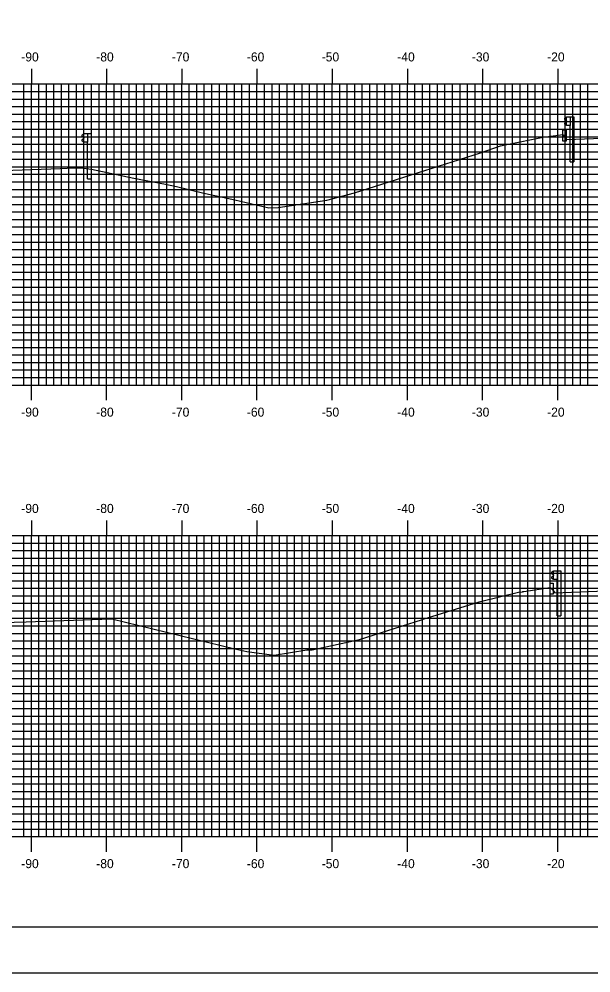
# Model space of a CAD drawing. Extents: x 858445 to 858788, y 364366 to 364586.
# Drawn here: x 858519.2 to 858595.3, y 364365.7 to 364492.4 of the extents above; entities that cross this region are included whole.
import ezdxf

# ---------------------------------------------------------------- set-up
doc = ezdxf.new("R2010")
doc.units = 0
for name, color, linetype in [('BORDER', 7, 'Continuous'), ('H_V ANNOTATION', 7, 'Continuous'), ('M_Guardrail', 7, 'Continuous'), ('MAJOR', 7, 'Continuous'), ('MINOR', 7, 'Continuous'), ('PLOT BOUNDARY', 7, 'Continuous'), ('S_Curb_Type_1', 7, 'Continuous'), ('S_Guardrail_Beam', 7, 'Continuous'), ('S_Roadway_Centerline', 7, 'Continuous')]:
    doc.layers.add(name, color=color, linetype=linetype)

msp = doc.modelspace()

# ---------------------------------------------------------------- linework, layer by layer
at = {"layer": 'BORDER'}
msp.add_lwpolyline([(858461.27, 364371.79), (858781.27, 364371.79), (858781.27, 364581.79), (858461.27, 364581.79)], close=True, dxfattribs=at)
at = {"layer": 'M_Guardrail'}
for p, q in [((858527.76, 364477.11), (858527.61, 364477.01)), ((858527.61, 364476.87), (858527.81, 364476.73)), ((858527.85, 364477.13), (858527.77, 364477.12)), ((858527.84, 364476.67), (858527.84, 364476.57)), ((858527.85, 364477.2), (858528.34, 364477.2)), ((858527.85, 364476.04), (858527.85, 364477.2)), ((858528.34, 364477.2), (858528.84, 364477.2)), ((858528.34, 364477.2), (858528.34, 364476.04)), ((858528.84, 364477.2), (858528.84, 364471.2)), ((858527.81, 364476.51), (858527.61, 364476.37)), ((858527.61, 364476.23), (858527.76, 364476.13)), ((858527.77, 364476.12), (858527.85, 364476.11)), ((858528.34, 364476.04), (858527.85, 364476.04)), ((858528.34, 364471.2), (858528.34, 364476.04)), ((858528.34, 364471.2), (858528.84, 364471.2))]:
    msp.add_line(p, q, dxfattribs=at)
for centre, major_axis, start_param, end_param in [((858527.66, 364476.94), (-0.0877, 0), 5.323254, 7.243116), ((858527.78, 364477.08), (-0.0417, 0), 4.886922, 5.323254), ((858527.76, 364476.67), (0.0789, 0), 0, 0.959931), ((858527.76, 364476.57), (0.0789, 0), 5.323254, 6.283185), ((858527.66, 364476.3), (-0.0877, 0), 5.323254, 7.243116), ((858527.78, 364476.16), (-0.0417, 0), 0.959931, 1.396263)]:
    msp.add_ellipse(centre, major_axis=major_axis, ratio=0.995501, start_param=start_param, end_param=end_param, dxfattribs=at)
at = {"layer": 'MAJOR'}
for p, q in [((858520.87, 364485.79), (858520.87, 364483.79)), ((858530.87, 364485.79), (858530.87, 364483.79)), ((858540.87, 364485.79), (858540.87, 364483.79)), ((858550.87, 364485.79), (858550.87, 364483.79)), ((858560.87, 364485.79), (858560.87, 364483.79)), ((858570.87, 364485.79), (858570.87, 364483.79)), ((858580.87, 364485.79), (858580.87, 364483.79)), ((858590.87, 364485.79), (858590.87, 364483.79)), ((858470.87, 364483.79), (858750.87, 364483.79)), ((858470.87, 364483.79), (858750.87, 364483.79)), ((858520.87, 364443.79), (858520.87, 364483.79)), ((858530.87, 364443.79), (858530.87, 364483.79)), ((858540.87, 364443.79), (858540.87, 364483.79)), ((858550.87, 364443.79), (858550.87, 364483.79)), ((858560.87, 364443.79), (858560.87, 364483.79)), ((858570.87, 364443.79), (858570.87, 364483.79)), ((858580.87, 364443.79), (858580.87, 364483.79)), ((858590.87, 364443.79), (858590.87, 364483.79)), ((858470.87, 364478.79), (858750.87, 364478.79)), ((858470.87, 364473.79), (858750.87, 364473.79)), ((858470.87, 364468.79), (858750.87, 364468.79)), ((858470.87, 364463.79), (858750.87, 364463.79)), ((858470.87, 364458.79), (858750.87, 364458.79)), ((858470.87, 364453.79), (858750.87, 364453.79)), ((858470.87, 364448.79), (858750.87, 364448.79)), ((858470.87, 364443.79), (858750.87, 364443.79)), ((858470.87, 364443.79), (858750.87, 364443.79)), ((858520.87, 364441.78), (858520.87, 364443.79)), ((858530.87, 364441.78), (858530.87, 364443.79)), ((858540.87, 364441.78), (858540.87, 364443.79)), ((858550.87, 364441.78), (858550.87, 364443.79)), ((858560.87, 364441.78), (858560.87, 364443.79)), ((858570.87, 364441.78), (858570.87, 364443.79)), ((858580.87, 364441.78), (858580.87, 364443.79)), ((858590.87, 364441.78), (858590.87, 364443.79)), ((858520.87, 364425.79), (858520.87, 364423.79)), ((858530.87, 364425.79), (858530.87, 364423.79)), ((858540.87, 364425.79), (858540.87, 364423.79)), ((858550.87, 364425.79), (858550.87, 364423.79)), ((858560.87, 364425.79), (858560.87, 364423.79)), ((858570.87, 364425.79), (858570.87, 364423.79)), ((858580.87, 364425.79), (858580.87, 364423.79)), ((858590.87, 364425.79), (858590.87, 364423.79)), ((858470.87, 364423.79), (858750.87, 364423.79)), ((858470.87, 364423.79), (858750.87, 364423.79)), ((858520.87, 364383.79), (858520.87, 364423.79)), ((858530.87, 364383.79), (858530.87, 364423.79)), ((858540.87, 364383.79), (858540.87, 364423.79)), ((858550.87, 364383.79), (858550.87, 364423.79)), ((858560.87, 364383.79), (858560.87, 364423.79)), ((858570.87, 364383.79), (858570.87, 364423.79)), ((858580.87, 364383.79), (858580.87, 364423.79)), ((858590.87, 364383.79), (858590.87, 364423.79)), ((858470.87, 364418.79), (858750.87, 364418.79)), ((858470.87, 364413.79), (858750.87, 364413.79)), ((858470.87, 364408.79), (858750.87, 364408.79)), ((858470.87, 364403.79), (858750.87, 364403.79)), ((858470.87, 364398.79), (858750.87, 364398.79)), ((858470.87, 364393.79), (858750.87, 364393.79)), ((858470.87, 364388.79), (858750.87, 364388.79)), ((858470.87, 364383.79), (858750.87, 364383.79)), ((858470.87, 364383.79), (858750.87, 364383.79)), ((858520.87, 364381.78), (858520.87, 364383.79)), ((858530.87, 364381.78), (858530.87, 364383.79)), ((858540.87, 364381.78), (858540.87, 364383.79)), ((858550.87, 364381.78), (858550.87, 364383.79)), ((858560.87, 364381.78), (858560.87, 364383.79)), ((858570.87, 364381.78), (858570.87, 364383.79)), ((858580.87, 364381.78), (858580.87, 364383.79)), ((858590.87, 364381.78), (858590.87, 364383.79))]:
    msp.add_line(p, q, dxfattribs=at)
at = {"layer": 'MINOR'}
for p, q in [((858519.87, 364443.79), (858519.87, 364483.79)), ((858521.87, 364443.79), (858521.87, 364483.79)), ((858522.87, 364443.79), (858522.87, 364483.79)), ((858523.87, 364443.79), (858523.87, 364483.79)), ((858524.87, 364443.79), (858524.87, 364483.79)), ((858525.87, 364443.79), (858525.87, 364483.79)), ((858526.87, 364443.79), (858526.87, 364483.79)), ((858527.87, 364443.79), (858527.87, 364483.79)), ((858528.87, 364443.79), (858528.87, 364483.79)), ((858529.87, 364443.79), (858529.87, 364483.79)), ((858531.87, 364443.79), (858531.87, 364483.79)), ((858532.87, 364443.79), (858532.87, 364483.79)), ((858533.87, 364443.79), (858533.87, 364483.79)), ((858534.87, 364443.79), (858534.87, 364483.79)), ((858535.87, 364443.79), (858535.87, 364483.79)), ((858536.87, 364443.79), (858536.87, 364483.79)), ((858537.87, 364443.79), (858537.87, 364483.79)), ((858538.87, 364443.79), (858538.87, 364483.79)), ((858539.87, 364443.79), (858539.87, 364483.79)), ((858541.87, 364443.79), (858541.87, 364483.79)), ((858542.87, 364443.79), (858542.87, 364483.79)), ((858543.87, 364443.79), (858543.87, 364483.79)), ((858544.87, 364443.79), (858544.87, 364483.79)), ((858545.87, 364443.79), (858545.87, 364483.79)), ((858546.87, 364443.79), (858546.87, 364483.79)), ((858547.87, 364443.79), (858547.87, 364483.79)), ((858548.87, 364443.79), (858548.87, 364483.79)), ((858549.87, 364443.79), (858549.87, 364483.79)), ((858551.87, 364443.79), (858551.87, 364483.79)), ((858552.87, 364443.79), (858552.87, 364483.79)), ((858553.87, 364443.79), (858553.87, 364483.79)), ((858554.87, 364443.79), (858554.87, 364483.79)), ((858555.87, 364443.79), (858555.87, 364483.79)), ((858556.87, 364443.79), (858556.87, 364483.79)), ((858557.87, 364443.79), (858557.87, 364483.79)), ((858558.87, 364443.79), (858558.87, 364483.79)), ((858559.87, 364443.79), (858559.87, 364483.79)), ((858561.87, 364443.79), (858561.87, 364483.79)), ((858562.87, 364443.79), (858562.87, 364483.79)), ((858563.87, 364443.79), (858563.87, 364483.79)), ((858564.87, 364443.79), (858564.87, 364483.79)), ((858565.87, 364443.79), (858565.87, 364483.79)), ((858566.87, 364443.79), (858566.87, 364483.79)), ((858567.87, 364443.79), (858567.87, 364483.79)), ((858568.87, 364443.79), (858568.87, 364483.79)), ((858569.87, 364443.79), (858569.87, 364483.79)), ((858571.87, 364443.79), (858571.87, 364483.79)), ((858572.87, 364443.79), (858572.87, 364483.79)), ((858573.87, 364443.79), (858573.87, 364483.79)), ((858574.87, 364443.79), (858574.87, 364483.79)), ((858575.87, 364443.79), (858575.87, 364483.79)), ((858576.87, 364443.79), (858576.87, 364483.79)), ((858577.87, 364443.79), (858577.87, 364483.79)), ((858578.87, 364443.79), (858578.87, 364483.79)), ((858579.87, 364443.79), (858579.87, 364483.79)), ((858581.87, 364443.79), (858581.87, 364483.79)), ((858582.87, 364443.79), (858582.87, 364483.79)), ((858583.87, 364443.79), (858583.87, 364483.79)), ((858584.87, 364443.79), (858584.87, 364483.79)), ((858585.87, 364443.79), (858585.87, 364483.79)), ((858586.87, 364443.79), (858586.87, 364483.79)), ((858587.87, 364443.79), (858587.87, 364483.79)), ((858588.87, 364443.79), (858588.87, 364483.79)), ((858589.87, 364443.79), (858589.87, 364483.79)), ((858591.87, 364443.79), (858591.87, 364483.79)), ((858592.87, 364443.79), (858592.87, 364483.79)), ((858593.87, 364443.79), (858593.87, 364483.79)), ((858594.87, 364443.79), (858594.87, 364483.79)), ((858470.87, 364482.79), (858750.87, 364482.79)), ((858470.87, 364481.79), (858750.87, 364481.79)), ((858470.87, 364480.79), (858750.87, 364480.79)), ((858470.87, 364479.79), (858750.87, 364479.79)), ((858470.87, 364477.79), (858750.87, 364477.79)), ((858470.87, 364476.79), (858750.87, 364476.79)), ((858470.87, 364475.79), (858750.87, 364475.79)), ((858470.87, 364474.79), (858750.87, 364474.79)), ((858470.87, 364472.79), (858750.87, 364472.79)), ((858470.87, 364471.79), (858750.87, 364471.79)), ((858470.87, 364470.79), (858750.87, 364470.79)), ((858470.87, 364469.79), (858750.87, 364469.79)), ((858470.87, 364467.79), (858750.87, 364467.79)), ((858470.87, 364466.79), (858750.87, 364466.79)), ((858470.87, 364465.79), (858750.87, 364465.79)), ((858470.87, 364464.79), (858750.87, 364464.79)), ((858470.87, 364462.79), (858750.87, 364462.79)), ((858470.87, 364461.79), (858750.87, 364461.79)), ((858470.87, 364460.79), (858750.87, 364460.79)), ((858470.87, 364459.79), (858750.87, 364459.79)), ((858470.87, 364457.79), (858750.87, 364457.79)), ((858470.87, 364456.79), (858750.87, 364456.79)), ((858470.87, 364455.79), (858750.87, 364455.79)), ((858470.87, 364454.79), (858750.87, 364454.79)), ((858470.87, 364452.79), (858750.87, 364452.79)), ((858470.87, 364451.79), (858750.87, 364451.79)), ((858470.87, 364450.79), (858750.87, 364450.79)), ((858470.87, 364449.79), (858750.87, 364449.79)), ((858470.87, 364447.79), (858750.87, 364447.79)), ((858470.87, 364446.79), (858750.87, 364446.79)), ((858470.87, 364445.79), (858750.87, 364445.79)), ((858470.87, 364444.79), (858750.87, 364444.79)), ((858519.87, 364383.79), (858519.87, 364423.79)), ((858521.87, 364383.79), (858521.87, 364423.79)), ((858522.87, 364383.79), (858522.87, 364423.79)), ((858523.87, 364383.79), (858523.87, 364423.79)), ((858524.87, 364383.79), (858524.87, 364423.79)), ((858525.87, 364383.79), (858525.87, 364423.79)), ((858526.87, 364383.79), (858526.87, 364423.79)), ((858527.87, 364383.79), (858527.87, 364423.79)), ((858528.87, 364383.79), (858528.87, 364423.79)), ((858529.87, 364383.79), (858529.87, 364423.79)), ((858531.87, 364383.79), (858531.87, 364423.79)), ((858532.87, 364383.79), (858532.87, 364423.79)), ((858533.87, 364383.79), (858533.87, 364423.79)), ((858534.87, 364383.79), (858534.87, 364423.79)), ((858535.87, 364383.79), (858535.87, 364423.79)), ((858536.87, 364383.79), (858536.87, 364423.79)), ((858537.87, 364383.79), (858537.87, 364423.79)), ((858538.87, 364383.79), (858538.87, 364423.79)), ((858539.87, 364383.79), (858539.87, 364423.79)), ((858541.87, 364383.79), (858541.87, 364423.79)), ((858542.87, 364383.79), (858542.87, 364423.79)), ((858543.87, 364383.79), (858543.87, 364423.79)), ((858544.87, 364383.79), (858544.87, 364423.79)), ((858545.87, 364383.79), (858545.87, 364423.79)), ((858546.87, 364383.79), (858546.87, 364423.79)), ((858547.87, 364383.79), (858547.87, 364423.79)), ((858548.87, 364383.79), (858548.87, 364423.79)), ((858549.87, 364383.79), (858549.87, 364423.79)), ((858551.87, 364383.79), (858551.87, 364423.79)), ((858552.87, 364383.79), (858552.87, 364423.79)), ((858553.87, 364383.79), (858553.87, 364423.79)), ((858554.87, 364383.79), (858554.87, 364423.79)), ((858555.87, 364383.79), (858555.87, 364423.79)), ((858556.87, 364383.79), (858556.87, 364423.79)), ((858557.87, 364383.79), (858557.87, 364423.79)), ((858558.87, 364383.79), (858558.87, 364423.79)), ((858559.87, 364383.79), (858559.87, 364423.79)), ((858561.87, 364383.79), (858561.87, 364423.79)), ((858562.87, 364383.79), (858562.87, 364423.79)), ((858563.87, 364383.79), (858563.87, 364423.79)), ((858564.87, 364383.79), (858564.87, 364423.79)), ((858565.87, 364383.79), (858565.87, 364423.79)), ((858566.87, 364383.79), (858566.87, 364423.79)), ((858567.87, 364383.79), (858567.87, 364423.79)), ((858568.87, 364383.79), (858568.87, 364423.79)), ((858569.87, 364383.79), (858569.87, 364423.79)), ((858571.87, 364383.79), (858571.87, 364423.79)), ((858572.87, 364383.79), (858572.87, 364423.79)), ((858573.87, 364383.79), (858573.87, 364423.79)), ((858574.87, 364383.79), (858574.87, 364423.79)), ((858575.87, 364383.79), (858575.87, 364423.79)), ((858576.87, 364383.79), (858576.87, 364423.79)), ((858577.87, 364383.79), (858577.87, 364423.79)), ((858578.87, 364383.79), (858578.87, 364423.79)), ((858579.87, 364383.79), (858579.87, 364423.79)), ((858581.87, 364383.79), (858581.87, 364423.79)), ((858582.87, 364383.79), (858582.87, 364423.79)), ((858583.87, 364383.79), (858583.87, 364423.79)), ((858584.87, 364383.79), (858584.87, 364423.79)), ((858585.87, 364383.79), (858585.87, 364423.79)), ((858586.87, 364383.79), (858586.87, 364423.79)), ((858587.87, 364383.79), (858587.87, 364423.79)), ((858588.87, 364383.79), (858588.87, 364423.79)), ((858589.87, 364383.79), (858589.87, 364423.79)), ((858591.87, 364383.79), (858591.87, 364423.79)), ((858592.87, 364383.79), (858592.87, 364423.79)), ((858593.87, 364383.79), (858593.87, 364423.79)), ((858594.87, 364383.79), (858594.87, 364423.79)), ((858470.87, 364422.79), (858750.87, 364422.79)), ((858470.87, 364421.79), (858750.87, 364421.79)), ((858470.87, 364420.79), (858750.87, 364420.79)), ((858470.87, 364419.79), (858750.87, 364419.79)), ((858470.87, 364417.79), (858750.87, 364417.79)), ((858470.87, 364416.79), (858750.87, 364416.79)), ((858470.87, 364415.79), (858750.87, 364415.79)), ((858470.87, 364414.79), (858750.87, 364414.79)), ((858470.87, 364412.79), (858750.87, 364412.79)), ((858470.87, 364411.79), (858750.87, 364411.79)), ((858470.87, 364410.79), (858750.87, 364410.79)), ((858470.87, 364409.79), (858750.87, 364409.79)), ((858470.87, 364407.79), (858750.87, 364407.79)), ((858470.87, 364406.79), (858750.87, 364406.79)), ((858470.87, 364405.79), (858750.87, 364405.79)), ((858470.87, 364404.79), (858750.87, 364404.79)), ((858470.87, 364402.79), (858750.87, 364402.79)), ((858470.87, 364401.79), (858750.87, 364401.79)), ((858470.87, 364400.79), (858750.87, 364400.79)), ((858470.87, 364399.79), (858750.87, 364399.79)), ((858470.87, 364397.79), (858750.87, 364397.79)), ((858470.87, 364396.79), (858750.87, 364396.79)), ((858470.87, 364395.79), (858750.87, 364395.79)), ((858470.87, 364394.79), (858750.87, 364394.79)), ((858470.87, 364392.79), (858750.87, 364392.79)), ((858470.87, 364391.79), (858750.87, 364391.79)), ((858470.87, 364390.79), (858750.87, 364390.79)), ((858470.87, 364389.79), (858750.87, 364389.79)), ((858470.87, 364387.79), (858750.87, 364387.79)), ((858470.87, 364386.79), (858750.87, 364386.79)), ((858470.87, 364385.79), (858750.87, 364385.79)), ((858470.87, 364384.79), (858750.87, 364384.79))]:
    msp.add_line(p, q, dxfattribs=at)
at = {"layer": 'PLOT BOUNDARY'}
msp.add_lwpolyline([(858445.09, 364365.67), (858785.09, 364365.67), (858785.09, 364585.67), (858445.09, 364585.67)], close=True, dxfattribs=at)
at = {"layer": 'S_Curb_Type_1'}
for points in [[(858591.56, 364477.68), (858591.98, 364477.68), (858591.98, 364476.18), (858591.56, 364476.18)], [(858591.56, 364477.68), (858591.98, 364477.68), (858591.98, 364476.18), (858591.56, 364476.18)], [(858589.84, 364417.48), (858590.26, 364417.48), (858590.26, 364415.98), (858589.84, 364415.98)], [(858589.84, 364417.48), (858590.26, 364417.48), (858590.26, 364415.98), (858589.84, 364415.98)]]:
    msp.add_lwpolyline(points, close=True, dxfattribs=at)
at = {"layer": 'S_Guardrail_Beam'}
for p, q in [((858591.93, 364479.33), (858591.79, 364479.23)), ((858591.93, 364479.33), (858591.79, 364479.23)), ((858591.79, 364479.09), (858591.98, 364478.95)), ((858591.79, 364479.09), (858591.98, 364478.95)), ((858592.03, 364479.35), (858591.95, 364479.34)), ((858592.03, 364479.35), (858591.95, 364479.34)), ((858592.03, 364479.43), (858592.52, 364479.43)), ((858592.03, 364478.26), (858592.03, 364479.43)), ((858592.03, 364479.43), (858592.52, 364479.43)), ((858592.03, 364478.26), (858592.03, 364479.43)), ((858592.52, 364479.43), (858593.01, 364479.43)), ((858592.52, 364479.43), (858592.52, 364478.26)), ((858592.52, 364479.43), (858593.01, 364479.43)), ((858592.52, 364479.43), (858592.52, 364478.26)), ((858593.01, 364479.43), (858593.01, 364473.43)), ((858593.01, 364479.43), (858593.01, 364473.43)), ((858591.98, 364478.73), (858591.79, 364478.6)), ((858591.98, 364478.73), (858591.79, 364478.6)), ((858591.79, 364478.45), (858591.93, 364478.35)), ((858591.79, 364478.45), (858591.93, 364478.35)), ((858591.95, 364478.35), (858592.03, 364478.33)), ((858591.95, 364478.35), (858592.03, 364478.33)), ((858592.01, 364478.89), (858592.01, 364478.8)), ((858592.01, 364478.89), (858592.01, 364478.8)), ((858592.52, 364478.26), (858592.03, 364478.26)), ((858592.52, 364478.26), (858592.03, 364478.26)), ((858592.52, 364473.43), (858592.52, 364478.26)), ((858592.52, 364473.43), (858592.52, 364478.26)), ((858592.52, 364473.43), (858593.01, 364473.43)), ((858592.52, 364473.43), (858593.01, 364473.43)), ((858590.2, 364419.01), (858590.06, 364418.91)), ((858590.2, 364419.01), (858590.06, 364418.91)), ((858590.06, 364418.76), (858590.25, 364418.63)), ((858590.06, 364418.76), (858590.25, 364418.63)), ((858590.25, 364418.41), (858590.06, 364418.27)), ((858590.25, 364418.41), (858590.06, 364418.27)), ((858590.3, 364419.03), (858590.22, 364419.01)), ((858590.3, 364419.03), (858590.22, 364419.01)), ((858590.28, 364418.56), (858590.28, 364418.47)), ((858590.28, 364418.56), (858590.28, 364418.47)), ((858590.3, 364419.1), (858590.79, 364419.1)), ((858590.3, 364417.94), (858590.3, 364419.1)), ((858590.3, 364419.1), (858590.79, 364419.1)), ((858590.3, 364417.94), (858590.3, 364419.1)), ((858590.79, 364419.1), (858591.28, 364419.1)), ((858590.79, 364419.1), (858590.79, 364417.94)), ((858590.79, 364419.1), (858591.28, 364419.1)), ((858590.79, 364419.1), (858590.79, 364417.94)), ((858591.28, 364419.1), (858591.28, 364413.1)), ((858591.28, 364419.1), (858591.28, 364413.1)), ((858590.06, 364418.13), (858590.2, 364418.03)), ((858590.06, 364418.13), (858590.2, 364418.03)), ((858590.22, 364418.02), (858590.3, 364418.01)), ((858590.22, 364418.02), (858590.3, 364418.01)), ((858590.79, 364417.94), (858590.3, 364417.94)), ((858590.79, 364417.94), (858590.3, 364417.94)), ((858590.79, 364413.1), (858590.79, 364417.94)), ((858590.79, 364413.1), (858590.79, 364417.94)), ((858590.79, 364413.1), (858591.28, 364413.1)), ((858590.79, 364413.1), (858591.28, 364413.1))]:
    msp.add_line(p, q, dxfattribs=at)
for centre, major_axis, start_param, end_param in [((858591.84, 364479.16), (-0.0877, 0), 5.323254, 7.243116), ((858591.84, 364479.16), (-0.0877, 0), 5.323254, 7.243116), ((858591.95, 364479.3), (-0.0417, 0), 4.886922, 5.323254), ((858591.95, 364479.3), (-0.0417, 0), 4.886922, 5.323254), ((858591.84, 364478.53), (-0.0877, 0), 5.323254, 7.243116), ((858591.84, 364478.53), (-0.0877, 0), 5.323254, 7.243116), ((858591.95, 364478.39), (-0.0417, 0), 0.959931, 1.396263), ((858591.95, 364478.39), (-0.0417, 0), 0.959931, 1.396263), ((858591.94, 364478.89), (0.0789, 0), 0, 0.959931), ((858591.94, 364478.89), (0.0789, 0), 0, 0.959931), ((858591.94, 364478.8), (0.0789, 0), 5.323254, 6.283185), ((858591.94, 364478.8), (0.0789, 0), 5.323254, 6.283185), ((858590.11, 364418.84), (-0.0877, 0), 5.323254, 7.243116), ((858590.11, 364418.84), (-0.0877, 0), 5.323254, 7.243116), ((858590.11, 364418.2), (-0.0877, 0), 5.323254, 7.243116), ((858590.11, 364418.2), (-0.0877, 0), 5.323254, 7.243116), ((858590.22, 364418.97), (-0.0417, 0), 4.886922, 5.323254), ((858590.22, 364418.97), (-0.0417, 0), 4.886922, 5.323254), ((858590.21, 364418.56), (0.0789, 0), 0, 0.959931), ((858590.21, 364418.56), (0.0789, 0), 0, 0.959931), ((858590.21, 364418.47), (0.0789, 0), 5.323254, 6.283185), ((858590.21, 364418.47), (0.0789, 0), 5.323254, 6.283185), ((858590.22, 364418.06), (-0.0417, 0), 0.959931, 1.396263), ((858590.22, 364418.06), (-0.0417, 0), 0.959931, 1.396263)]:
    msp.add_ellipse(centre, major_axis=major_axis, ratio=0.995501, start_param=start_param, end_param=end_param, dxfattribs=at)
at = {"layer": 'S_Roadway_Centerline'}
for points in [[(858513.32, 364472.15), (858524.69, 364472.55), (858526.58, 364472.65), (858527.46, 364472.66), (858528.85, 364472.49), (858534.48, 364471.27), (858538.73, 364470.46), (858540.17, 364470.16), (858543.61, 364469.33), (858547.92, 364468.39), (858552.44, 364467.34), (858553.69, 364467.38), (858560.16, 364468.37), (858563.83, 364469.31), (858580.59, 364474.63), (858583.24, 364475.59), (858583.87, 364475.71), (858589.14, 364476.76), (858589.34, 364476.79), (858591.56, 364477.1), (858591.61, 364477.01), (858592.04, 364476.41), (858596.83, 364476.61)], [(858515.33, 364412.18), (858520.16, 364412.31), (858531.49, 364412.71), (858531.59, 364412.72), (858547.93, 364408.74), (858549.52, 364408.38), (858553.14, 364407.88), (858557.5, 364408.58), (858558.22, 364408.58), (858564.52, 364409.98), (858572.9, 364412.65), (858572.97, 364412.66), (858580.4, 364414.99), (858585.84, 364416.29), (858585.85, 364416.29), (858585.86, 364416.26), (858586.17, 364416.33), (858586.22, 364416.34), (858586.35, 364416.36), (858589.84, 364416.9), (858590.27, 364416.49), (858590.49, 364416.19), (858597.18, 364416.46)]]:
    msp.add_lwpolyline(points, dxfattribs=at)

# ---------------------------------------------------------------- texts
at = {"layer": 'H_V ANNOTATION'}
for s, p in [('-90', (858519.53, 364486.79)), ('-80', (858529.5, 364486.79)), ('-70', (858539.56, 364486.79)), ('-60', (858549.53, 364486.79)), ('-50', (858559.48, 364486.79)), ('-40', (858569.53, 364486.79)), ('-30', (858579.45, 364486.79)), ('-20', (858589.46, 364486.79)), ('-90', (858519.53, 364439.59)), ('-80', (858529.5, 364439.59)), ('-70', (858539.56, 364439.59)), ('-60', (858549.53, 364439.59)), ('-50', (858559.48, 364439.59)), ('-40', (858569.53, 364439.59)), ('-30', (858579.45, 364439.59)), ('-20', (858589.46, 364439.59)), ('-90', (858519.53, 364426.79)), ('-80', (858529.5, 364426.79)), ('-70', (858539.56, 364426.79)), ('-60', (858549.53, 364426.79)), ('-50', (858559.48, 364426.79)), ('-40', (858569.53, 364426.79)), ('-30', (858579.45, 364426.79)), ('-20', (858589.46, 364426.79)), ('-90', (858519.53, 364379.59)), ('-80', (858529.5, 364379.59)), ('-70', (858539.56, 364379.59)), ('-60', (858549.53, 364379.59)), ('-50', (858559.48, 364379.59)), ('-40', (858569.53, 364379.59)), ('-30', (858579.45, 364379.59)), ('-20', (858589.46, 364379.59))]:
    msp.add_text(s, height=1.2, dxfattribs=at).set_placement(p)

doc.saveas('drawing.dxf')
